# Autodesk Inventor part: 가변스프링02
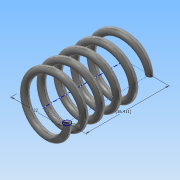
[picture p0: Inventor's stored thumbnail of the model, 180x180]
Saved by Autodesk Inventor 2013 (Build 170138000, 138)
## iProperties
Created: 2014-07
Part Number: 가변스프링02
Material: 강철, 탄소
Document SubType Name: Modeling
Designer: SEMTLE01_MAIN
Density: 7.87 g/cm^3
Mass: 18.8881 g
Surface Area: 32.5243 cm^2
Volume: 2.40001 cm^3
Author: SEMTLE01_MAIN
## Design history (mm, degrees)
sketch "스케치1"
  geometry: L1 (0, 0)-(11, 0); L2 (11, 0)-(11, 36.411); L3 (11, 36.411)-(0, 36.411); L4 (0, 36.411)-(0, 0); C1 r 1.5 at (11, 0)
  constraints: 8 end point, 2 parallel, 1 centre point, 1 coincident, 1 horizontal, 1 perpendicular
  dimensions: "d0" = 3 diameter of C1; "d2" = 22 diameter of L1.end L4; "d3" = 36.4112 distance of L1.end L2.end (derived)
feature "코일1" pitch "d4" = 10; turns "d6" = 5; dims "d5" = 36.4112 (= d3), "d7" = 0, angle "d8" = 90 deg, angle "d9" = 90 deg, "d10" = 0, "d11" = 0
sketch "스케치2"
  geometry: L1 (-12.5, 0)-(-9.5, 0) reference; 1 further point
  constraints: 1 horizontal alignment
extrude "돌출1" cut sketch "스케치2" stored distance "d12" = 10; taper "d13" = 0 deg
node "작업 평면1"
sketch "스케치3"
  geometry: L1 (1.5, 0)-(-1.5, 0) reference; 1 further point
  constraints: 1 horizontal alignment
extrude "돌출2" cut sketch "스케치3" stored distance "d15" = 10; taper "d16" = 0 deg
node "솔리드1"
node "절단 모서리 투영1"
node "절단 모서리 투영2"
other parameters: "d14" = 0
